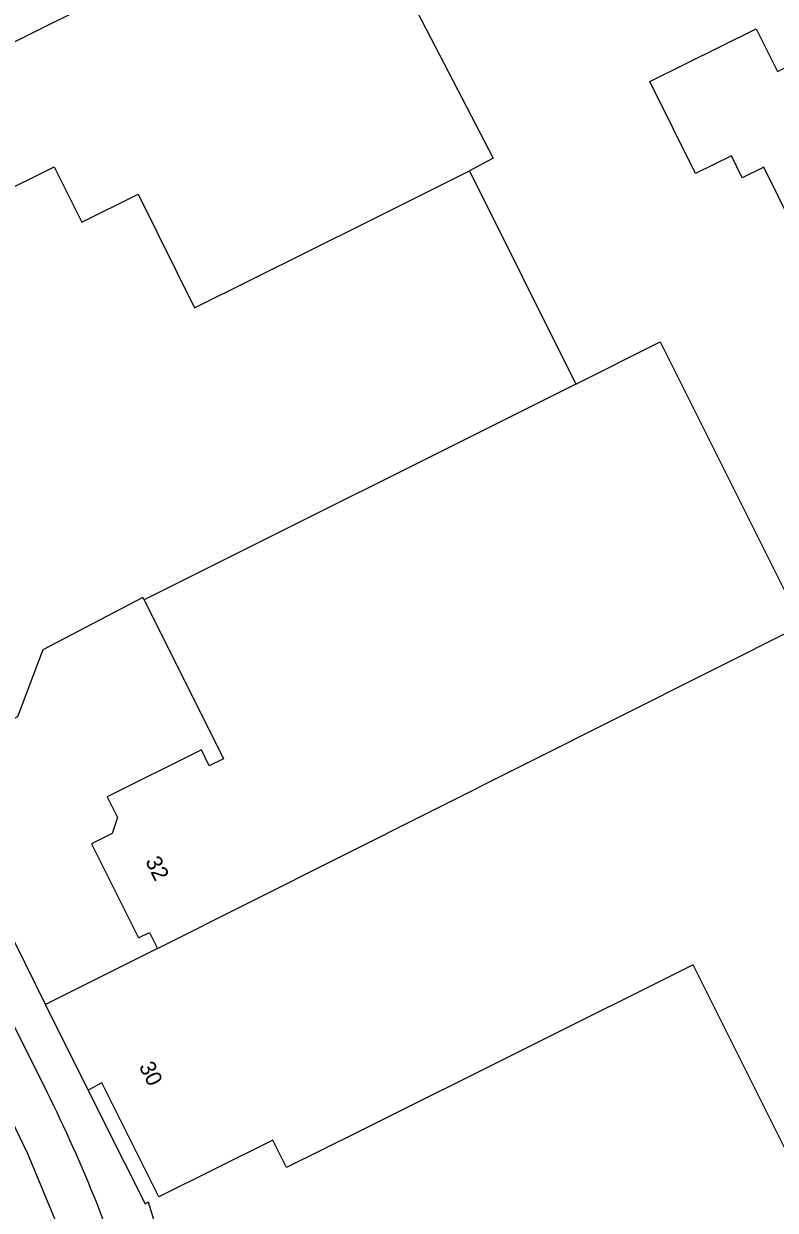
# Model space of a CAD drawing. Extents: x 157793 to 159380, y 380882 to 382313.
# Drawn here: x 158103.9 to 158151.1, y 381421.5 to 381496 of the extents above; entities that cross this region are included whole.
import ezdxf

# ---------------------------------------------------------------- set-up
doc = ezdxf.new("R2010")
doc.units = 0
for name, color, linetype in [('IMGEO_Pand', 7, 'Continuous'), ('IMGEO_Pand_nummerreeks', 7, 'Continuous'), ('IMGEO_Rijbaan_lokaal_gesloten', 7, 'Continuous'), ('IMGEO_Voetpad_open', 7, 'Continuous')]:
    doc.layers.add(name, color=color, linetype=linetype)

msp = doc.modelspace()

# ---------------------------------------------------------------- linework, layer by layer
at = {"layer": 'IMGEO_Pand'}
for points in [[(158124.2, 381505.225), (158116.498, 381501.399), (158113.682, 381500), (158098.358, 381492.375), (158092.512, 381489.464), (158088.796, 381487.614)], [(158124.2, 381505.225), (158126.91, 381500), (158133.378, 381487.53), (158131.883, 381486.744)], [(158150.358, 381486.974), (158149.006, 381486.306), (158148.329, 381487.677), (158146.075, 381486.564), (158143.205, 381492.34), (158145.4, 381493.431), (158149.877, 381495.655), (158151.207, 381492.977), (158157.113, 381495.892), (158159.329, 381491.402), (158157.977, 381490.735), (158159.757, 381487.128), (158155.274, 381484.915), (158152.138, 381483.367), (158150.358, 381486.974)], [(158087.87, 381478.262), (158101.906, 381485.251), (158102.017, 381485.306), (158102.095, 381485.148), (158105.818, 381486.996), (158107.541, 381483.524), (158111.085, 381485.283), (158114.629, 381478.142), (158125.429, 381483.508), (158131.883, 381486.744)], [(158131.883, 381486.744), (158138.549, 381473.356)], [(158138.549, 381473.356), (158143.854, 381475.996), (158152.732, 381458.23)], [(158138.549, 381473.356), (158111.452, 381459.814)], [(158111.452, 381459.814), (158111.381, 381459.956), (158105.1, 381456.683), (158103.521, 381452.469), (158101.422, 381451.35)], [(158111.452, 381459.814), (158116.446, 381449.835), (158115.551, 381449.39), (158115.052, 381450.392), (158109.144, 381447.45), (158109.791, 381446.152), (158109.454, 381445.147), (158108.155, 381444.5), (158111.096, 381438.591), (158111.79, 381438.937), (158112.296, 381437.92)], [(158112.296, 381437.92), (158152.732, 381458.23)], [(158154.582, 381454.526), (158165.775, 381432.125), (158151.804, 381425.141), (158145.928, 381436.906), (158124.878, 381426.406), (158120.403, 381424.174), (158119.541, 381425.901), (158112.381, 381422.33), (158108.81, 381429.501), (158107.949, 381429.043)], [(158112.296, 381437.92), (158105.266, 381434.42)], [(158107.949, 381429.043), (158105.266, 381434.42)]]:
    msp.add_lwpolyline(points, dxfattribs=at)
at = {"layer": 'IMGEO_Rijbaan_lokaal_gesloten'}
msp.add_lwpolyline([(158116.632, 381344.813), (158116.021, 381346.737), (158115.709, 381348.982), (158112.092, 381395.233), (158111.117, 381402.923), (158109.46, 381410.496), (158107.132, 381417.89), (158104.154, 381425.047), (158103.399, 381426.613), (158089.726, 381454.684), (158068.546, 381497.113)], dxfattribs=at)
at = {"layer": 'IMGEO_Voetpad_open'}
for points in [[(158105.373, 381428.915), (158098.454, 381442.769), (158091.734, 381456.357), (158091.541, 381456.746), (158086.441, 381467.033), (158086.232, 381467.454)], [(158105.266, 381434.42), (158100.082, 381444.906), (158097.743, 381449.563)], [(158107.949, 381429.043), (158108.918, 381427.086), (158111.525, 381421.906), (158111.72, 381422.014), (158113.913, 381414.881), (158115.678, 381415.029), (158116.513, 381403.112), (158117.076, 381396.038), (158117.953, 381384.662), (158118.264, 381380.414), (158118.967, 381370.804), (158119.481, 381364.938)]]:
    msp.add_lwpolyline(points, dxfattribs=at)
for centre, radius, start, end in [((158009.157, 381381.623), 107.21, 22.1062, 26.17493), ((158013.077, 381385.123), 102.277, 15.69762, 21.11606)]:
    msp.add_arc(centre, radius, start, end, dxfattribs=at)

# ---------------------------------------------------------------- texts
at = {"layer": 'IMGEO_Pand_nummerreeks'}
for s, rotation, p in [('32', 296.46024, (158111.512, 381443.411)), ('30', 296.47229, (158111.112, 381430.53))]:
    msp.add_text(s, height=1, rotation=rotation, dxfattribs=at).set_placement(p)

doc.saveas('drawing.dxf')
